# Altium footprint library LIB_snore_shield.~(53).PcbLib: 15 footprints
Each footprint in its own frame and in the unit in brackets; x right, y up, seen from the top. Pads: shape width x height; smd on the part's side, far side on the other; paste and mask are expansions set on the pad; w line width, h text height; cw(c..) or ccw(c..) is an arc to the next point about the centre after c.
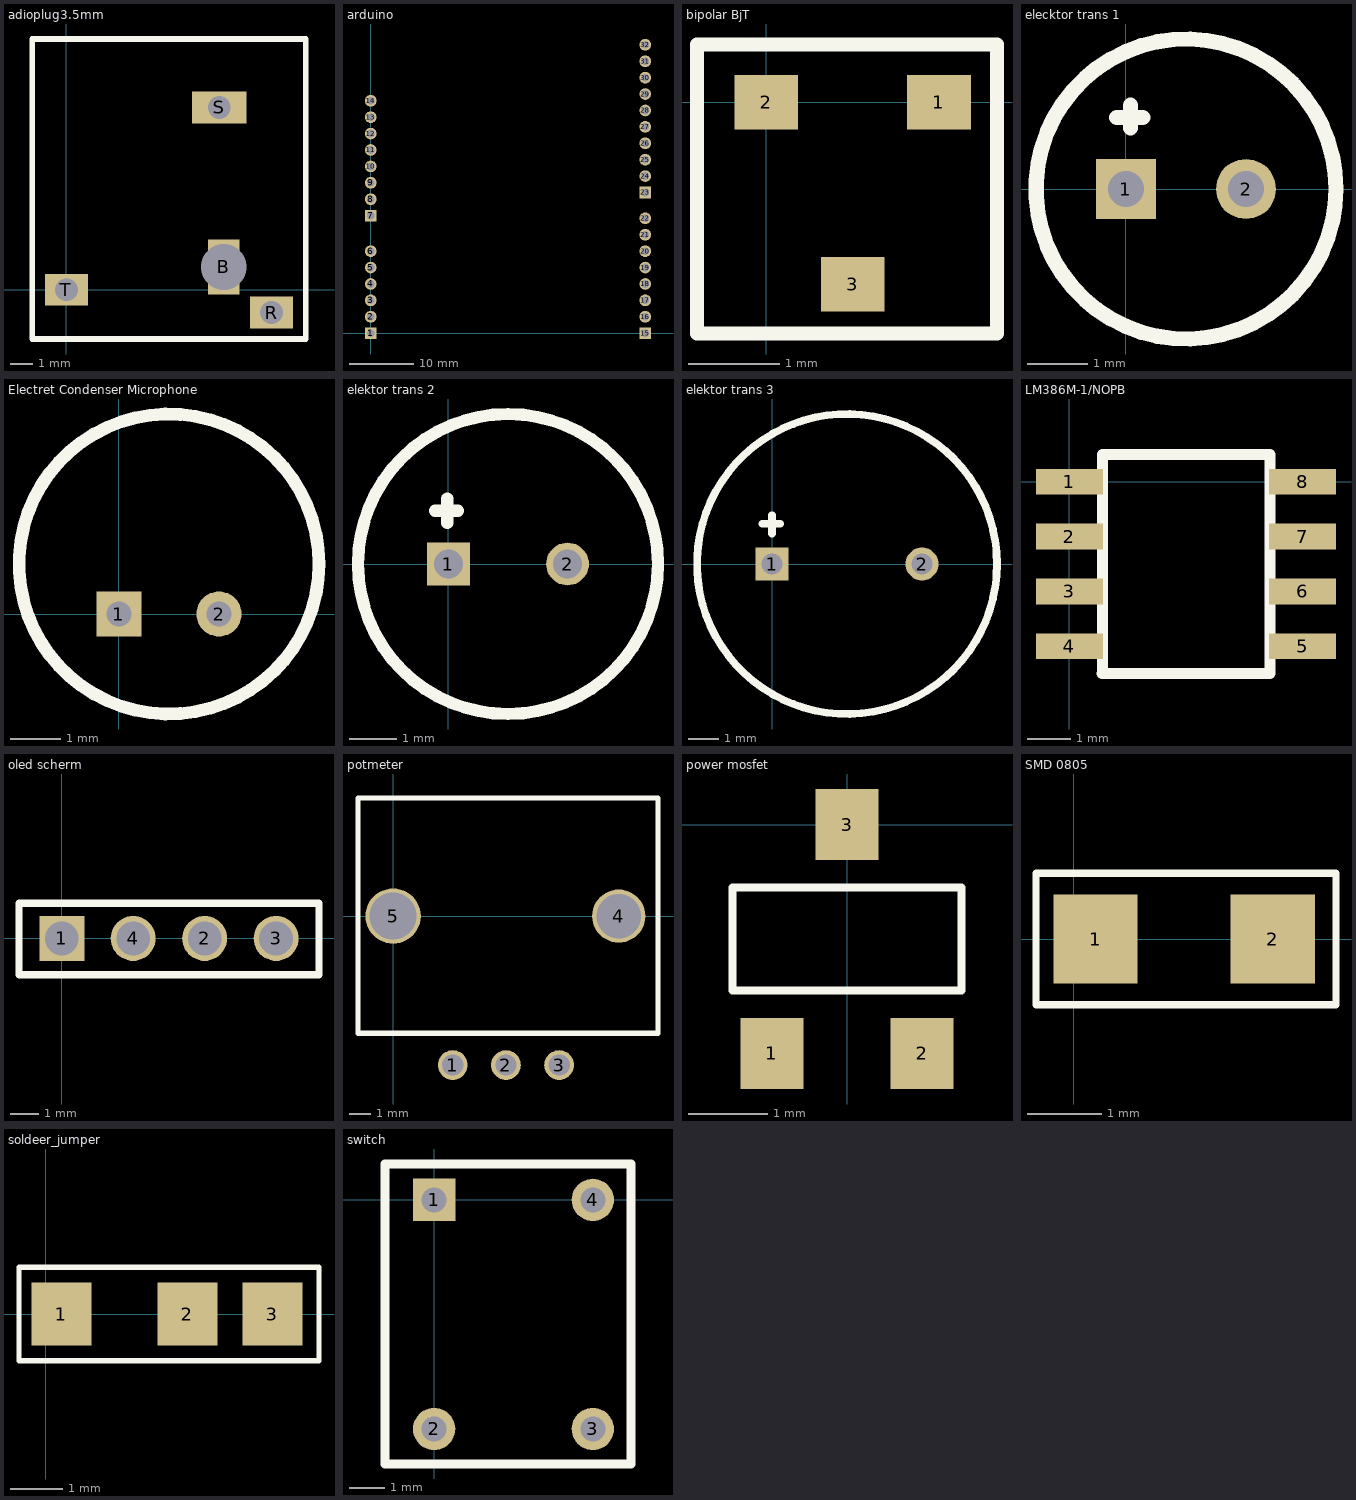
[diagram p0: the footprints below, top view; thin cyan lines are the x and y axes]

## adioplug3.5mm [mm]
pads (4):
  rect 1.4x2.4 hole 2 square: B(6.9,1)
  rect 1.9x1.4 hole 1 square: R(9,-1)
  rect 2.4x1.4 / inner rect 2.2x1.27 / far side rect 2.2x1.2 hole 1 square: S(6.7,8)
  rect 1.9x1.4 / inner rect 2.54x1.27 / far side rect 1.7x1.2 hole 1 square: T(0,0)
Top Overlay:
  lines w0.254: -1.5,-2.159 -1.5,11 10.5,11 10.5,-2.159 -1.5,-2.159

## arduino [mm]
pads (32):
  rect 1.8x1.8 hole 1.2: 1(0,0) 7(0,18.2) 15(42.5,0) 23(42.5,21.78)
  round 1.8 hole 1.2: 2(0,2.54) 3(0,5.08) 4(0,7.62) 5(0,10.16) 6(0,12.7) 8(0,20.74) 9(0,23.28) 10(0,25.82) 11(0,28.36) 12(0,30.9) 13(0,33.44) 14(0,35.98) 16(42.5,2.54) 17(42.5,5.08) 18(42.5,7.62) 19(42.5,10.16) 20(42.5,12.7) 21(42.5,15.24) 22(42.5,17.78) 24(42.5,24.32) 25(42.5,26.86) 26(42.5,29.4) 27(42.5,31.94) 28(42.5,34.48) 29(42.5,37.02) 30(42.5,39.56) 31(42.5,42.1) 32(42.5,44.64)

## bipolar BjT [mm]
pads (3):
  rect 0.7x0.6 smd: 1(1.9,0) 2(0,0) 3(0.95,-2)
Top Overlay:
  lines w0.154: -0.762,-2.54 -0.762,0.635 2.538,0.635 2.538,-2.54 -0.762,-2.54

## elecktor trans 1 [mm]
pads (2):
  rect 1x1 hole 0.6: 1(0,0)
  round 1 hole 0.6: 2(2,0)
Top Overlay:
  circle w0.254: c1,0 r2.5
  lines w0.254: -0.152,1.194 0.279,1.194 ; 0.076,1.016 0.076,1.397

## Electret Condenser Microphone [mm]
pads (2):
  rect 0.9x0.9 hole 0.5: 1(0,0)
  round 0.9 hole 0.5: 2(2,0)
Top Overlay:
  circle w0.254: c1,1 r3

## elektor trans 2 [mm]
pads (2):
  rect 0.9x0.9 hole 0.6: 1(0,0)
  round 0.9 hole 0.6: 2(2.5,0)
Top Overlay:
  circle w0.254: c1.25,0 r3.15
  lines w0.254: -0.279,1.118 0.203,1.118 ; -0.025,0.864 -0.025,1.372

## elektor trans 3 [mm]
pads (2):
  rect 1.1x1.1 hole 0.7: 1(0,0)
  round 1.1 hole 0.7: 2(5,0)
Top Overlay:
  circle w0.254: c2.5,0 r5
  lines w0.254: -0.33,1.346 0.279,1.346 ; 0,1.016 0,1.626

## LM386M-1/NOPB [mm]
pads (8):
  rect 1.55x0.6 smd: 1(0,0) 2(0,-1.27) 3(0,-2.54) 4(0,-3.81) 5(5.4,-3.81) 6(5.4,-2.54) 7(5.4,-1.27) 8(5.4,0)
Top Overlay:
  lines w0.254: 0.75,-4.445 4.65,-4.445 4.65,0.635 0.762,0.635 0.762,-0.635 0.762,-3.175 0.762,-4.445

## oled scherm [mm]
pads (4):
  rect 1.6x1.6 hole 1.2: 1(0,0)
  round 1.6 hole 1.2: 2(5.08,0) 3(7.62,0) 4(2.54,0)
Top Overlay:
  lines w0.254: -1.52,-1.29 -1.52,1.25 9.144,1.25 9.144,-1.29 -1.52,-1.29

## PCBComponent_1 [mm]

## potmeter [mm]
pads (5):
  round 1.4 hole 1: 1(2.8,-7) 2(5.3,-7)
  round 1.4 / inner oval 1.4x0.064 / far side round 1.4 hole 1: 3(7.8,-7)
  round 2.5 / inner oval 2.5x0.064 / far side round 2.5 hole 2.1: 4(10.6,0)
  round 2.6 / inner round 2.5 / far side round 2.5 hole 2.2: 5(0,0)
Top Overlay:
  lines w0.254: -1.651,-5.5 -1.651,5.549 12.446,5.549 12.446,-5.5 -1.651,-5.5

## power mosfet [mm]
pads (3):
  rect 0.8x0.9 smd: 1(-0.95,-2.9) 2(0.95,-2.9) 3(0,0)
Top Overlay:
  lines w0.1: -1.45,-2.1 1.45,-2.1 1.45,-0.8 -1.45,-0.8 -1.45,-2.1

## SMD 0805 [mm]
pads (2):
  rect 1.14x1.2 smd: 1(0.3,0) 2(2.7,0)
Top Overlay:
  lines w0.1: -0.508,-0.889 0.035,-0.889 0.797,-0.889 2.251,-0.889 2.667,-0.889 3.556,-0.889 3.556,0.889 -0.508,0.889 -0.508,-0.889

## soldeer_jumper [mm]
pads (3):
  rect 1.14x1.2 smd: 1(0.3,0) 2(2.7,0) 3(4.318,0)
Top Overlay:
  lines w0.1: -0.508,-0.889 5.207,-0.889 5.207,0.889 -0.508,0.889 -0.508,-0.889

## switch [mm]
pads (4):
  rect 1.2x1.2 hole 0.71: 1(0,0)
  round 1.2 hole 0.71: 2(0,-6.5) 3(4.5,-6.5) 4(4.5,0)
Top Overlay:
  lines w0.254: -1.397,-7.493 -1.397,1.016 5.588,1.016 5.588,-7.493 -1.397,-7.493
